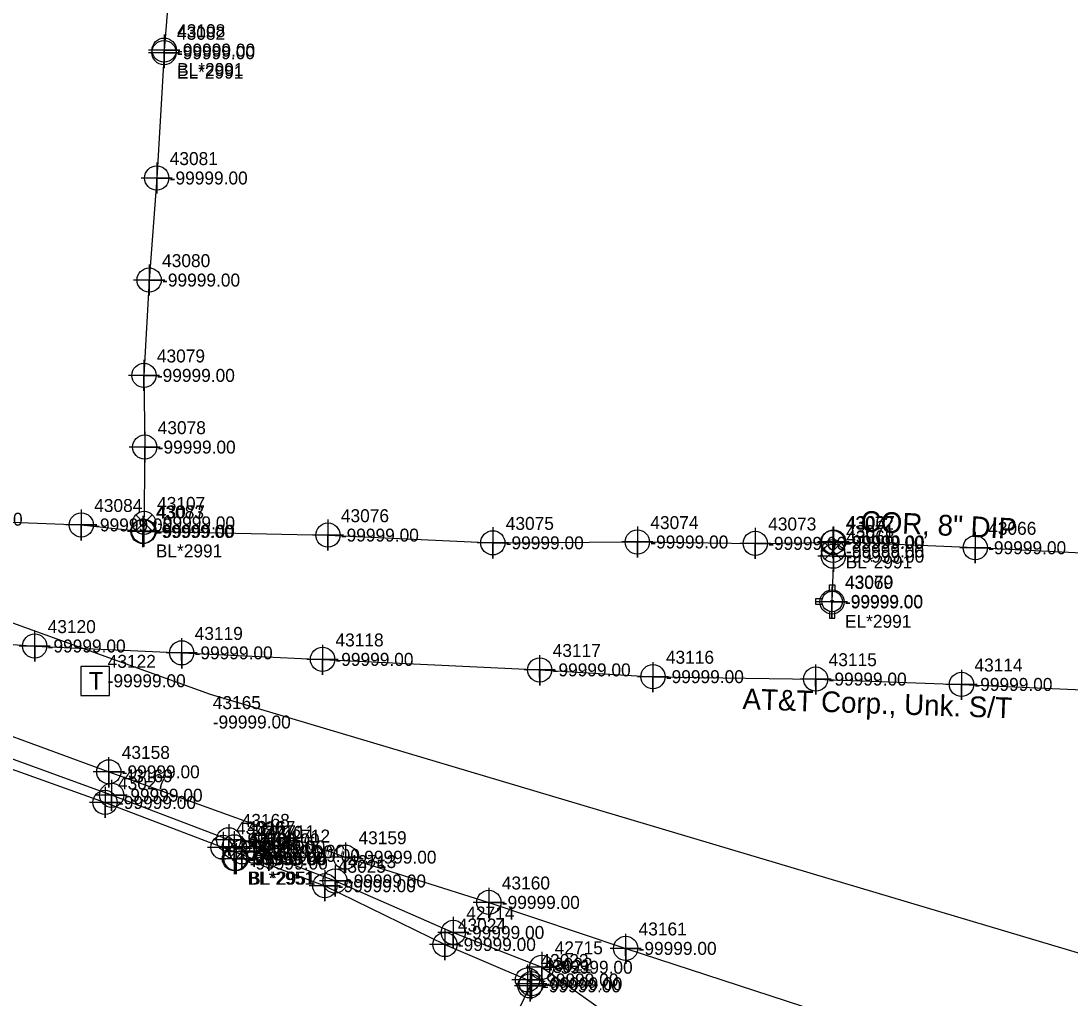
# Model space of a CAD drawing. Extents: x 2083698 to 2094313, y 743246 to 752873.
# Drawn here: x 2092936 to 2093138.5, y 746831.1 to 747019.8 of the extents above; entities that cross this region are included whole.
import ezdxf

# ---------------------------------------------------------------- set-up
doc = ezdxf.new("R2010")
doc.units = 0
for name, color, linetype in [('COGO Default Point Number', 7, 'Continuous'), ('Exist Property Iron Pin Leader', 7, 'Continuous'), ('Exist Property Iron Pin Text', 7, 'Continuous'), ('Exist Property Line', 7, 'Continuous'), ('Exist Property Monument Cogo Elevation', 7, 'Continuous'), ('Exist Property Monument Cogo Number', 7, 'Continuous'), ('Exist Property Monument Leader', 7, 'Continuous'), ('Exist Property Monument Text', 7, 'Continuous'), ('Exist Right of Way Easement Line Leader', 7, 'Continuous'), ('Exist Right of Way Easement Line Text', 7, 'Continuous'), ('Exist Right of Way Line', 7, 'Continuous'), ('Exist Right of Way Line Leader', 7, 'Continuous'), ('Exist Right of Way Line Text', 7, 'Continuous'), ('Exist Right of Way Monument Cogo Comment', 7, 'Continuous'), ('Exist Right of Way Monument Cogo Elevation', 7, 'Continuous'), ('Exist Right of Way Monument Cogo Number', 7, 'Continuous'), ('Exist Right of Way Width CELL', 7, 'Continuous'), ('Exist Roads EOP', 7, 'Continuous'), ('Exist Roads EOP Leader', 7, 'Continuous'), ('Exist Roads EOP Text', 7, 'Continuous'), ('Exist Utilities Power Tower Cogo Elevation', 7, 'Continuous'), ('Exist Utilities Power Tower Cogo Number', 7, 'Continuous'), ('Exist Utilities Power UG Cable SUE LOS B', 7, 'Continuous'), ('Exist Utilities Power UG Cable SUE LOS C', 7, 'Continuous'), ('Exist Utilities Telephone UG Conduit SUE LOS B', 7, 'Continuous'), ('Exist Utilities Telephone UG Conduit SUE LOS B Text', 7, 'Continuous'), ('Exist Utilities Water UG Line SUE LOS B', 7, 'Continuous'), ('Exist Utilities Water UG Line SUE LOS B Text', 7, 'Continuous'), ('Raster_Level_1', 7, 'Continuous'), ('Scratch_Level_2', 7, 'Continuous')]:
    doc.layers.add(name, color=color, linetype=linetype)

msp = doc.modelspace()

# ---------------------------------------------------------------- linework, layer by layer
at = {"layer": 'COGO Default Point Number'}
for points in [[(2092963.64, 747017.2), (2092963.64, 747011.2), (2092963.64, 747014.2), (2092966.64, 747014.2), (2092960.64, 747014.2)], [(2092963.61, 747016.7), (2092963.61, 747010.7), (2092963.61, 747013.7), (2092966.61, 747013.7), (2092960.61, 747013.7)], [(2092962.21, 746992.5), (2092962.21, 746986.5), (2092962.21, 746989.5), (2092965.21, 746989.5), (2092959.21, 746989.5)], [(2092960.74, 746972.79), (2092960.74, 746966.79), (2092960.74, 746969.79), (2092963.74, 746969.79), (2092957.74, 746969.79)], [(2092959.73, 746954.38), (2092959.73, 746948.38), (2092959.73, 746951.38), (2092962.73, 746951.38), (2092956.73, 746951.38)], [(2092959.89, 746940.53), (2092959.89, 746934.53), (2092959.89, 746937.53), (2092962.89, 746937.53), (2092956.89, 746937.53)], [(2092947.63, 746925.5), (2092947.63, 746919.5), (2092947.63, 746922.5), (2092950.63, 746922.5), (2092944.63, 746922.5)], [(2092959.53, 746924.23), (2092959.53, 746918.23), (2092959.53, 746921.23), (2092962.53, 746921.23), (2092956.53, 746921.23)], [(2092959.72, 746924.28), (2092959.72, 746918.28), (2092959.72, 746921.28), (2092962.72, 746921.28), (2092956.72, 746921.28)], [(2092995.25, 746923.53), (2092995.25, 746917.53), (2092995.25, 746920.53), (2092998.25, 746920.53), (2092992.25, 746920.53)], [(2093027.08, 746922.04), (2093027.08, 746916.04), (2093027.08, 746919.04), (2093030.08, 746919.04), (2093024.08, 746919.04)], [(2093054.99, 746922.2), (2093054.99, 746916.2), (2093054.99, 746919.2), (2093057.99, 746919.2), (2093051.99, 746919.2)], [(2093077.74, 746921.93), (2093077.74, 746915.93), (2093077.74, 746918.93), (2093080.74, 746918.93), (2093074.74, 746918.93)], [(2093092.71, 746922.1), (2093092.71, 746916.1), (2093092.71, 746919.1), (2093095.71, 746919.1), (2093089.71, 746919.1)], [(2093092.87, 746922.21), (2093092.87, 746916.21), (2093092.87, 746919.21), (2093095.87, 746919.21), (2093089.87, 746919.21)], [(2093120.21, 746921.09), (2093120.21, 746915.09), (2093120.21, 746918.09), (2093123.21, 746918.09), (2093117.21, 746918.09)], [(2093092.82, 746919.46), (2093092.82, 746913.46), (2093092.82, 746916.46), (2093095.82, 746916.46), (2093089.82, 746916.46)], [(2093092.56, 746910.63), (2093092.56, 746904.63), (2093092.56, 746907.63), (2093095.56, 746907.63), (2093089.56, 746907.63)]]:
    msp.add_lwpolyline(points, dxfattribs=at)
for centre in [(2092963.61, 747013.7), (2092963.64, 747014.2), (2092962.21, 746989.5), (2092960.74, 746969.79), (2092959.73, 746951.38), (2092959.89, 746937.53), (2092947.63, 746922.5), (2092959.53, 746921.23), (2092959.72, 746921.28), (2092995.25, 746920.53), (2093027.08, 746919.04), (2093054.99, 746919.2), (2093077.74, 746918.93), (2093092.71, 746919.1), (2093092.87, 746919.21), (2093120.21, 746918.09), (2093092.82, 746916.46), (2093092.56, 746907.63)]:
    msp.add_circle(centre, 2.34, dxfattribs=at)
at = {"layer": 'Exist Property Iron Pin Text'}
for points in [[(2092953.5, 746873.29), (2092953.5, 746867.29), (2092953.5, 746870.29), (2092956.5, 746870.29), (2092950.5, 746870.29)], [(2092952.23, 746871.9), (2092952.23, 746865.9), (2092952.23, 746868.9), (2092955.23, 746868.9), (2092949.23, 746868.9)], [(2092975.01, 746863.21), (2092975.01, 746857.21), (2092975.01, 746860.21), (2092978.01, 746860.21), (2092972.01, 746860.21)], [(2092976.1, 746864.68), (2092976.1, 746858.68), (2092976.1, 746861.68), (2092979.1, 746861.68), (2092973.1, 746861.68)], [(2092977.17, 746863.32), (2092977.17, 746857.32), (2092977.17, 746860.32), (2092980.17, 746860.32), (2092974.17, 746860.32)], [(2092977.22, 746861.03), (2092977.22, 746855.03), (2092977.22, 746858.03), (2092980.22, 746858.03), (2092974.22, 746858.03)], [(2092977.52, 746861.03), (2092977.52, 746855.03), (2092977.52, 746858.03), (2092980.52, 746858.03), (2092974.52, 746858.03)], [(2092978.66, 746862.36), (2092978.66, 746856.36), (2092978.66, 746859.36), (2092981.66, 746859.36), (2092975.66, 746859.36)], [(2092981, 746862.48), (2092981, 746856.48), (2092981, 746859.48), (2092984, 746859.48), (2092978, 746859.48)], [(2092983.87, 746861.66), (2092983.87, 746855.66), (2092983.87, 746858.66), (2092986.87, 746858.66), (2092980.87, 746858.66)], [(2092994.66, 746855.82), (2092994.66, 746849.82), (2092994.66, 746852.82), (2092997.66, 746852.82), (2092991.66, 746852.82)], [(2092996.63, 746856.73), (2092996.63, 746850.73), (2092996.63, 746853.73), (2092999.63, 746853.73), (2092993.63, 746853.73)], [(2093019.46, 746846.79), (2093019.46, 746840.79), (2093019.46, 746843.79), (2093022.46, 746843.79), (2093016.46, 746843.79)], [(2093017.84, 746844.46), (2093017.84, 746838.46), (2093017.84, 746841.46), (2093020.84, 746841.46), (2093014.84, 746841.46)], [(2093036.53, 746840.07), (2093036.53, 746834.07), (2093036.53, 746837.07), (2093039.53, 746837.07), (2093033.53, 746837.07)], [(2093033.78, 746837.63), (2093033.78, 746831.63), (2093033.78, 746834.63), (2093036.78, 746834.63), (2093030.78, 746834.63)], [(2093034.53, 746836.88), (2093034.53, 746830.88), (2093034.53, 746833.88), (2093037.53, 746833.88), (2093031.53, 746833.88)], [(2093034.27, 746836.47), (2093034.27, 746830.47), (2093034.27, 746833.47), (2093037.27, 746833.47), (2093031.27, 746833.47)]]:
    msp.add_lwpolyline(points, dxfattribs=at)
for centre in [(2092952.23, 746868.9), (2092953.5, 746870.29), (2092976.1, 746861.68), (2092975.01, 746860.21), (2092977.17, 746860.32), (2092978.66, 746859.36), (2092981, 746859.48), (2092983.87, 746858.66), (2092977.22, 746858.03), (2092977.52, 746858.03), (2092994.66, 746852.82), (2092996.63, 746853.73), (2093019.46, 746843.79), (2093017.84, 746841.46), (2093036.53, 746837.07), (2093033.78, 746834.63), (2093034.27, 746833.47), (2093034.53, 746833.88)]:
    msp.add_circle(centre, 2.34, dxfattribs=at)
at = {"layer": 'Exist Right of Way Line Text'}
for points in [[(2092938.62, 746901.92), (2092938.65, 746896.11), (2092938.64, 746899.11), (2092941.65, 746899.11), (2092935.65, 746899.11)], [(2092967, 746900.6), (2092967.03, 746894.79), (2092967.01, 746897.79), (2092970.03, 746897.79), (2092964.03, 746897.79)], [(2092994.18, 746899.34), (2092994.21, 746893.53), (2092994.19, 746896.53), (2092997.21, 746896.53), (2092991.21, 746896.53)], [(2093036.11, 746897.32), (2093036.14, 746891.5), (2093036.12, 746894.5), (2093039.14, 746894.5), (2093033.14, 746894.5)], [(2093057.96, 746896.01), (2093057.99, 746890.19), (2093057.97, 746893.19), (2093060.99, 746893.19), (2093054.99, 746893.19)], [(2093089.39, 746895.53), (2093089.42, 746889.72), (2093089.4, 746892.72), (2093092.42, 746892.72), (2093086.42, 746892.72)], [(2093117.53, 746894.51), (2093117.56, 746888.69), (2093117.54, 746891.69), (2093120.56, 746891.69), (2093114.56, 746891.69)], [(2092952.92, 746877.62), (2092952.95, 746871.81), (2092952.93, 746874.81), (2092955.95, 746874.81), (2092949.95, 746874.81)], [(2092998.62, 746861.14), (2092998.65, 746855.33), (2092998.64, 746858.33), (2093001.65, 746858.33), (2092995.65, 746858.33)], [(2093026.29, 746852.4), (2093026.32, 746846.59), (2093026.31, 746849.59), (2093029.32, 746849.59), (2093023.32, 746849.59)], [(2093052.69, 746843.52), (2093052.73, 746837.71), (2093052.71, 746840.71), (2093055.73, 746840.71), (2093049.73, 746840.71)]]:
    msp.add_lwpolyline(points, dxfattribs=at)
for centre in [(2092938.65, 746899.11), (2092967.03, 746897.79), (2092994.21, 746896.53), (2093036.14, 746894.5), (2093057.99, 746893.19), (2093089.42, 746892.72), (2093117.56, 746891.69), (2092952.95, 746874.81), (2092998.65, 746858.33), (2093026.32, 746849.59), (2093052.73, 746840.71)]:
    msp.add_circle(centre, 2.34, dxfattribs=at)
at = {"layer": 'Exist Right of Way Monument Cogo Number'}
msp.add_line((2092950.24, 746892.4), (2092950.24, 746892.4), dxfattribs=at)
msp.add_lwpolyline([(2092947.52, 746889.57), (2092953.11, 746889.57), (2092953.11, 746895.16), (2092947.52, 746895.16), (2092947.52, 746889.57)], dxfattribs=at)
at = {"layer": 'Exist Roads EOP'}
for points in [[(2092961.35, 746924.47), (2092958.2, 746921.33), (2092959.77, 746922.9), (2092961.35, 746921.33), (2092958.2, 746924.47)], [(2093094.35, 746919.04), (2093091.2, 746915.89), (2093092.77, 746917.46), (2093094.35, 746915.89), (2093091.2, 746919.04)]]:
    msp.add_lwpolyline(points, dxfattribs=at)
for centre in [(2092959.77, 746922.9), (2093092.77, 746917.46)]:
    msp.add_circle(centre, 2.23, dxfattribs=at)
at = {"layer": 'Exist Utilities Power UG Cable SUE LOS B'}
for points in [[(2092723.34, 746956.69), (2092734.13, 746952.11), (2092746.7, 746947.35), (2092771.29, 746937.67), (2092797.88, 746928.04), (2092820.13, 746919.69), (2092879.52, 746895.35), (2092905.67, 746885.55), (2092952.23, 746868.9), (2092975.01, 746860.21), (2092994.66, 746852.82), (2093017.84, 746841.46), (2093033.78, 746834.63), (2093034.53, 746833.88), (2093034.27, 746833.47), (2093030.6, 746825.95), (2093029.06, 746821.9)], [(2092977.22, 746858.03), (2092977.17, 746860.32), (2092976.1, 746861.68), (2092953.5, 746870.29), (2092905.32, 746887.81), (2092880.36, 746897.3), (2092854.4, 746907.17), (2092833.9, 746915.23), (2092831.19, 746915.74), (2092828.87, 746914.77)], [(2092977.52, 746858.03), (2092978.66, 746859.36), (2092981, 746859.48), (2092983.87, 746858.66), (2092996.63, 746853.73), (2093019.46, 746843.79), (2093036.53, 746837.07), (2093052.53, 746825.76), (2093078.78, 746815.71), (2093105.54, 746808.07), (2093123.18, 746802.59), (2093142.77, 746796.15), (2093143.35, 746794.93)]]:
    msp.add_lwpolyline(points, dxfattribs=at)
at = {"layer": 'Exist Utilities Power UG Cable SUE LOS C'}
msp.add_lwpolyline([(2091387.72, 747754.05), (2091459.29, 747488.14), (2091734.16, 747369.44), (2092190.29, 747172.26), (2092598.52, 747024.9), (2092972.51, 746889.78), (2093316.78, 746787.16), (2093711.24, 746532.37)], dxfattribs=at)
at = {"layer": 'Exist Utilities Telephone UG Conduit SUE LOS B'}
for points in [[(2092711.05, 746980.24), (2092714.78, 746968.82), (2092733.97, 746954.44), (2092747.49, 746948.95), (2092771.83, 746940.25), (2092799.92, 746930.67), (2092821.68, 746924.67), (2092847.55, 746915), (2092863.87, 746908.07), (2092905.27, 746892.32), (2092952.95, 746874.81), (2092998.65, 746858.33), (2093026.32, 746849.59), (2093052.73, 746840.71), (2093130.42, 746815.32), (2093158.34, 746805.93)], [(2092918.55, 746900.6), (2092938.65, 746899.11), (2092967.03, 746897.79), (2092994.21, 746896.53), (2093036.14, 746894.5), (2093057.99, 746893.19), (2093089.42, 746892.72), (2093117.56, 746891.69), (2093142.38, 746890.57)]]:
    msp.add_lwpolyline(points, dxfattribs=at)
at = {"layer": 'Exist Utilities Water UG Line SUE LOS B'}
for points in [[(2092969.39, 747070.29), (2092968.93, 747060.62), (2092965.48, 747037.18), (2092963.64, 747014.2)], [(2092963.61, 747013.7), (2092962.21, 746989.5), (2092960.74, 746969.79), (2092959.73, 746951.38), (2092959.89, 746937.53), (2092959.72, 746921.28)], [(2092963.64, 747014.2), (2092963.64, 747014.2)], [(2092693.91, 746935.26), (2092715.99, 746935.02), (2092728.33, 746934.79), (2092750.2, 746934.08), (2092761.23, 746933.22), (2092776.89, 746933.87), (2092823.97, 746930.41), (2092847.33, 746926.22), (2092856.36, 746926.47), (2092872.3, 746925.66), (2092898.38, 746922.88), (2092918.76, 746923.6), (2092947.63, 746922.5), (2092959.53, 746921.23)], [(2092959.72, 746921.28), (2092995.25, 746920.53), (2093027.08, 746919.04), (2093054.99, 746919.2), (2093077.74, 746918.93), (2093092.71, 746919.1)], [(2093092.87, 746919.21), (2093092.82, 746916.46), (2093092.56, 746907.63)], [(2093144.67, 746916.85), (2093120.21, 746918.09), (2093092.87, 746919.21)]]:
    msp.add_lwpolyline(points, dxfattribs=at)
at = {"layer": 'Raster_Level_1'}
msp.add_line((2093092.59, 746907.72), (2093092.59, 746907.72), dxfattribs=at)
for points in [[(2093092.08, 746909.63), (2093092.08, 746910.92), (2093093.1, 746910.92), (2093093.1, 746909.61)], [(2093090.68, 746908.23), (2093089.39, 746908.23), (2093089.39, 746907.21), (2093090.68, 746907.21)], [(2093092.08, 746905.81), (2093092.08, 746904.52), (2093093.1, 746904.52), (2093093.1, 746905.83)]]:
    msp.add_lwpolyline(points, dxfattribs=at)
for radius in [1.98, 0.243]:
    msp.add_circle((2093092.59, 746907.72), radius, dxfattribs=at)

# ---------------------------------------------------------------- texts
at = {"layer": 'Exist Property Iron Pin Leader'}
for s, p in [('43169', (2092956, 746872.79)), ('43027', (2092954.73, 746871.4)), ('43026', (2092977.51, 746862.71)), ('43168', (2092978.6, 746864.18)), ('43167', (2092979.67, 746862.82)), ('43166', (2092979.72, 746860.53)), ('42709', (2092980.02, 746860.53)), ('42710', (2092981.16, 746861.86)), ('42711', (2092983.5, 746861.98)), ('42712', (2092986.37, 746861.16)), ('43025', (2092997.16, 746855.32)), ('42713', (2092999.13, 746856.23)), ('42714', (2093021.96, 746846.29)), ('43024', (2093020.34, 746843.96)), ('42715', (2093039.03, 746839.57)), ('43023', (2093036.28, 746837.13)), ('43022', (2093037.03, 746836.38)), ('43021', (2093036.77, 746835.97))]:
    msp.add_text(s, height=2.5, dxfattribs=at).set_placement(p)
at = {"layer": 'Exist Property Line'}
for p in [(2092966.11, 747012.45), (2092966.14, 747012.95), (2092964.71, 746988.25), (2092963.24, 746968.54), (2092962.23, 746950.13), (2092962.39, 746936.28), (2092921.26, 746922.35), (2092950.13, 746921.25), (2092962.03, 746919.98), (2092962.22, 746920.03), (2092997.75, 746919.28), (2093029.58, 746917.79), (2093057.49, 746917.95), (2093080.24, 746917.68), (2093095.21, 746917.85), (2093095.37, 746917.96), (2093095.32, 746915.21), (2093122.71, 746916.84), (2093095.06, 746906.38)]:
    msp.add_text('-99999.00', height=2.5, dxfattribs=at).set_placement(p)
at = {"layer": 'Exist Property Monument Cogo Elevation'}
msp.add_text('-99999.00', height=2.5, dxfattribs=at).set_placement((2092980.17, 746855.93))
at = {"layer": 'Exist Property Monument Cogo Number'}
msp.add_text('42708', height=2.5, dxfattribs=at).set_placement((2092980.17, 746859.68))
at = {"layer": 'Exist Property Monument Leader'}
for p in [(2092979.72, 746853.03), (2092980.02, 746853.03)]:
    msp.add_text('BL*2951', height=2.5, dxfattribs=at).set_placement(p)
at = {"layer": 'Exist Property Monument Text'}
for p in [(2092956, 746869.04), (2092954.73, 746867.65), (2092978.6, 746860.43), (2092977.51, 746858.96), (2092979.67, 746859.07), (2092979.72, 746856.78), (2092980.02, 746856.78), (2092981.16, 746858.11), (2092983.5, 746858.23), (2092986.37, 746857.41), (2092999.13, 746852.48), (2092997.16, 746851.57), (2093021.96, 746842.54), (2093020.34, 746840.21), (2093039.03, 746835.82), (2093036.28, 746833.38), (2093036.77, 746832.22), (2093037.03, 746832.63)]:
    msp.add_text('-99999.00', height=2.5, dxfattribs=at).set_placement(p)
at = {"layer": 'Exist Right of Way Easement Line Leader'}
msp.add_text('-99999.00', height=2.5, dxfattribs=at).set_placement((2093095.09, 746906.47))
at = {"layer": 'Exist Right of Way Easement Line Text'}
msp.add_text('43070', height=2.5, dxfattribs=at).set_placement((2093095.09, 746910.22))
at = {"layer": 'Exist Right of Way Line'}
for s, p in [('43108', (2092966.14, 747016.7)), ('43082', (2092966.11, 747016.2)), ('43081', (2092964.71, 746992)), ('43080', (2092963.24, 746972.29)), ('43079', (2092962.23, 746953.88)), ('43078', (2092962.39, 746940.03)), ('43084', (2092950.13, 746925)), ('43083', (2092962.03, 746923.73)), ('43077', (2092962.22, 746923.78)), ('43076', (2092997.75, 746923.03)), ('43075', (2093029.58, 746921.54)), ('43074', (2093057.49, 746921.7)), ('43073', (2093080.24, 746921.43)), ('43072', (2093095.21, 746921.6)), ('43067', (2093095.37, 746921.71)), ('43066', (2093122.71, 746920.59)), ('43068', (2093095.32, 746918.96)), ('43069', (2093095.06, 746910.13))]:
    msp.add_text(s, height=2.5, dxfattribs=at).set_placement(p)
at = {"layer": 'Exist Right of Way Line Leader'}
for s, p in [('43120', (2092941.15, 746901.61)), ('43119', (2092969.53, 746900.29)), ('43118', (2092996.71, 746899.03)), ('43117', (2093038.64, 746897)), ('43116', (2093060.49, 746895.69)), ('43115', (2093091.92, 746895.22)), ('43114', (2093120.06, 746894.19)), ('43158', (2092955.45, 746877.31)), ('43159', (2093001.15, 746860.83)), ('43160', (2093028.82, 746852.09)), ('43161', (2093055.23, 746843.21))]:
    msp.add_text(s, height=2.5, dxfattribs=at).set_placement(p)
at = {"layer": 'Exist Right of Way Monument Cogo Comment'}
msp.add_text('-99999.00', height=2.5, dxfattribs=at).set_placement((2092952.74, 746891.15))
at = {"layer": 'Exist Right of Way Monument Cogo Elevation'}
msp.add_text('43122', height=2.5, dxfattribs=at).set_placement((2092952.74, 746894.9))
at = {"layer": 'Exist Right of Way Monument Cogo Number'}
msp.add_text('T', height=3.42, dxfattribs=at).set_placement((2092949.11, 746890.68))
at = {"layer": 'Exist Right of Way Width CELL'}
for s, p in [('EL*2991', (2092966.11, 747008.7)), ('BL*2991', (2092966.14, 747009.2)), ('BL*2991', (2092962.03, 746916.23)), ('BL*2991', (2093095.21, 746914.1)), ('EL*2991', (2093095.06, 746902.63))]:
    msp.add_text(s, height=2.5, dxfattribs=at).set_placement(p)
at = {"layer": 'Exist Roads EOP Leader'}
for p in [(2092962.27, 746921.65), (2093095.27, 746916.21)]:
    msp.add_text('-99999.00', height=2.5, dxfattribs=at).set_placement(p)
at = {"layer": 'Exist Roads EOP Text'}
for s, p in [('43107', (2092962.27, 746925.4)), ('43071', (2093095.27, 746919.96))]:
    msp.add_text(s, height=2.5, dxfattribs=at).set_placement(p)
at = {"layer": 'Exist Utilities Power Tower Cogo Elevation'}
msp.add_text('-99999.00', height=2.5, dxfattribs=at).set_placement((2092973.02, 746883.18))
at = {"layer": 'Exist Utilities Power Tower Cogo Number'}
msp.add_text('43165', height=2.5, dxfattribs=at).set_placement((2092973.02, 746886.93))
at = {"layer": 'Exist Utilities Telephone UG Conduit SUE LOS B Text'}
msp.add_text('AT&T Corp., Unk. S/T', height=4, rotation=358.0295, dxfattribs=at).set_placement((2093075.24, 746886.93))
at = {"layer": 'Exist Utilities Water UG Line SUE LOS B Text'}
msp.add_text('COR, 8" DIP', height=4, rotation=357.1513, dxfattribs=at).set_placement((2093098.03, 746921.25))
at = {"layer": 'Scratch_Level_2'}
for p in [(2092941.15, 746897.86), (2092969.53, 746896.54), (2092996.71, 746895.28), (2093038.64, 746893.25), (2093060.49, 746891.94), (2093091.92, 746891.47), (2093120.06, 746890.44), (2092955.45, 746873.56), (2093001.15, 746857.08), (2093028.82, 746848.34), (2093055.23, 746839.46)]:
    msp.add_text('-99999.00', height=2.5, dxfattribs=at).set_placement(p)

doc.saveas('drawing.dxf')
